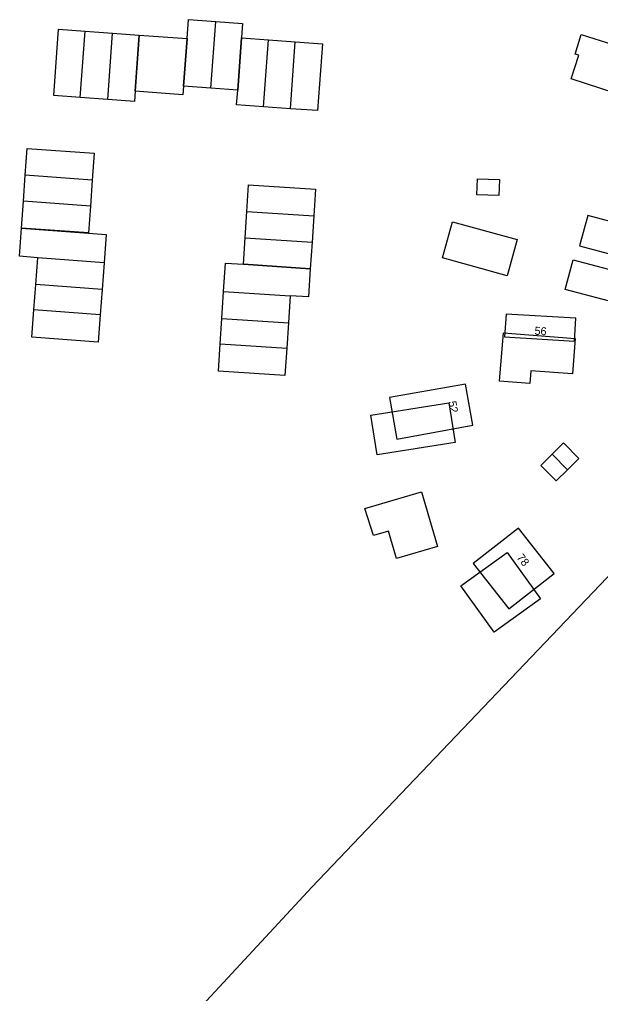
# Model space of a CAD drawing. Extents: x 159451 to 160663, y 388402 to 389723.
# Drawn here: x 160156.5 to 160229.1, y 389378.7 to 389500.3 of the extents above; entities that cross this region are included whole.
import ezdxf

# ---------------------------------------------------------------- set-up
doc = ezdxf.new("R2010")
doc.units = 0
for name, color, linetype in [('IMGEO_Groenvoorziening', 7, 'Continuous'), ('IMGEO_Pand', 7, 'Continuous'), ('IMGEO_Pand_nummerreeks', 7, 'Continuous'), ('IMGEO_Pand_vergunning_verleend', 7, 'Continuous')]:
    doc.layers.add(name, color=color, linetype=linetype)

msp = doc.modelspace()

# ---------------------------------------------------------------- linework, layer by layer
at = {"layer": 'IMGEO_Groenvoorziening'}
msp.add_lwpolyline([(160405.31, 389464.95), (160351.63, 389481.36), (160342.65, 389466.76), (160292.24, 389495.35), (160260.8, 389462.93), (160193.04, 389391.96), (160160.93, 389357.29)], dxfattribs=at)
at = {"layer": 'IMGEO_Pand'}
for points in [[(160240.12, 389472.47), (160227.53, 389475.83), (160226.52, 389472.04), (160239.12, 389468.67), (160240.12, 389472.47)], [(160226.06, 389462.98), (160217.33, 389463.5), (160217.15, 389460.66), (160225.88, 389460.14), (160226.06, 389462.98)], [(160202.76, 389453.09), (160203.67, 389447.9), (160213.16, 389449.65), (160212.26, 389454.75), (160202.76, 389453.09)], [(160213.24, 389432.36), (160217.67, 389426.68), (160223.33, 389431.12), (160218.9, 389436.78), (160213.24, 389432.36)]]:
    msp.add_lwpolyline(points, dxfattribs=at)
at = {"layer": 'IMGEO_Pand_vergunning_verleend'}
for points in [[(160177.46, 389497.91), (160177.63, 389500.3), (160181.04, 389500.05)], [(160180.44, 389491.72), (160181.04, 389500.05)], [(160181.04, 389500.05), (160184.39, 389499.81), (160184.26, 389497.99)], [(160164.11, 389490.56), (160160.8, 389490.8), (160161.39, 389499.08), (160164.71, 389498.84)], [(160164.11, 389490.56), (160164.71, 389498.84)], [(160164.71, 389498.84), (160168.16, 389498.59)], [(160167.56, 389490.31), (160168.16, 389498.59)], [(160168.16, 389498.59), (160171.49, 389498.34)], [(160170.99, 389491.33), (160170.99, 389491.33), (160171.49, 389498.34)], [(160171.49, 389498.34), (160170.99, 389491.33)], [(160171.49, 389498.34), (160177.46, 389497.91)], [(160225.46, 389492.87), (160226.41, 389495.84), (160225.95, 389495.99), (160226.73, 389498.44), (160233.07, 389496.41), (160232.26, 389493.88), (160231.88, 389494), (160230.95, 389491.1), (160225.46, 389492.87)], [(160177.46, 389497.91), (160176.95, 389490.89), (160170.99, 389491.33)], [(160180.44, 389491.72), (160177.03, 389491.97), (160177.46, 389497.91)], [(160183.79, 389491.48), (160184.26, 389497.99), (160184.26, 389497.99)], [(160184.26, 389497.99), (160183.79, 389491.48)], [(160184.26, 389497.99), (160187.63, 389497.75)], [(160187.02, 389489.4), (160187.63, 389497.75)], [(160187.63, 389497.75), (160190.98, 389497.5)], [(160190.38, 389489.16), (160190.98, 389497.5)], [(160190.98, 389497.5), (160194.38, 389497.26), (160193.78, 389488.92), (160190.38, 389489.16)], [(160170.99, 389491.33), (160170.9, 389490.07), (160167.56, 389490.31)], [(160183.79, 389491.48), (160180.44, 389491.72)], [(160187.02, 389489.4), (160183.66, 389489.65), (160183.79, 389491.48)], [(160167.56, 389490.31), (160164.11, 389490.56)], [(160190.38, 389489.16), (160187.02, 389489.4)], [(160157.25, 389480.84), (160157.5, 389484.2), (160165.86, 389483.6), (160165.62, 389480.24)], [(160157.02, 389477.6), (160157.25, 389480.84)], [(160165.62, 389480.24), (160157.25, 389480.84)], [(160165.62, 389480.24), (160165.38, 389477)], [(160213.69, 389478.42), (160213.76, 389480.41), (160216.49, 389480.32), (160216.42, 389478.32), (160213.69, 389478.42)], [(160184.94, 389476.31), (160185.16, 389479.64), (160193.52, 389479.1), (160193.3, 389475.76)], [(160156.78, 389474.25), (160157.02, 389477.6)], [(160165.38, 389477), (160157.02, 389477.6)], [(160165.38, 389477), (160165.14, 389473.65), (160156.78, 389474.25)], [(160184.73, 389473.05), (160184.94, 389476.31)], [(160184.94, 389476.31), (160193.3, 389475.76)], [(160193.3, 389475.76), (160193.08, 389472.5)], [(160209.38, 389470.53), (160210.64, 389475.05), (160218.72, 389472.81), (160217.46, 389468.29), (160209.38, 389470.53)], [(160158.81, 389470.55), (160156.52, 389470.73), (160156.78, 389474.25)], [(160156.78, 389474.25), (160167.36, 389473.46), (160167.09, 389469.93)], [(160184.51, 389469.73), (160184.73, 389473.05)], [(160184.73, 389473.05), (160193.08, 389472.5)], [(160193.08, 389472.5), (160192.86, 389469.18)], [(160158.56, 389467.22), (160158.81, 389470.55)], [(160167.09, 389469.93), (160158.81, 389470.55)], [(160224.72, 389466.58), (160225.7, 389470.29), (160238.18, 389466.99), (160237.2, 389463.29), (160224.72, 389466.58)], [(160167.09, 389469.93), (160166.84, 389466.6)], [(160182.03, 389466.35), (160182.26, 389469.88), (160184.51, 389469.73)], [(160184.51, 389469.73), (160192.86, 389469.18)], [(160192.86, 389469.18), (160184.51, 389469.73), (160184.51, 389469.73)], [(160192.86, 389469.18), (160192.63, 389465.66), (160190.36, 389465.81)], [(160158.32, 389464.04), (160158.56, 389467.22)], [(160166.84, 389466.6), (160158.56, 389467.22)], [(160166.84, 389466.6), (160166.61, 389463.42)], [(160181.81, 389462.95), (160182.03, 389466.35)], [(160182.03, 389466.35), (160190.36, 389465.81)], [(160190.36, 389465.81), (160190.13, 389462.4)], [(160166.61, 389463.42), (160166.35, 389460.02), (160158.07, 389460.64), (160158.32, 389464.04)], [(160166.61, 389463.42), (160158.32, 389464.04)], [(160181.6, 389459.79), (160181.81, 389462.95)], [(160181.81, 389462.95), (160190.13, 389462.4)], [(160190.13, 389462.4), (160189.93, 389459.25)], [(160216.53, 389455.13), (160216.99, 389461.15), (160225.98, 389460.46), (160225.64, 389456.03), (160220.43, 389456.43), (160220.31, 389454.84), (160216.53, 389455.13)], [(160189.93, 389459.25), (160189.7, 389455.84), (160181.38, 389456.39), (160181.6, 389459.79)], [(160181.6, 389459.79), (160189.93, 389459.25)], [(160200.44, 389450.89), (160210.16, 389452.44), (160210.95, 389447.48), (160201.24, 389445.93), (160200.44, 389450.89)], [(160223.08, 389446.02), (160224.49, 389447.42), (160226.41, 389445.48), (160225, 389444.08)], [(160225, 389444.08), (160223.59, 389442.68), (160221.67, 389444.62), (160223.08, 389446.02)], [(160223.08, 389446.02), (160225, 389444.08)], [(160199.68, 389439.25), (160206.78, 389441.32), (160208.77, 389434.49), (160203.62, 389432.99), (160202.62, 389436.41), (160200.76, 389435.87), (160199.68, 389439.25)], [(160211.68, 389429.57), (160217.45, 389433.75), (160221.62, 389427.97), (160215.85, 389423.8), (160211.68, 389429.57)]]:
    msp.add_lwpolyline(points, dxfattribs=at)

# ---------------------------------------------------------------- texts
at = {"layer": 'IMGEO_Pand_nummerreeks'}
for s, rotation, p in [('56', 356.631, (160220.87, 389460.94)), ('52', 279.9406, (160210.11, 389452.57)), ('78', 308.0556, (160218.61, 389433.09))]:
    msp.add_text(s, height=1, rotation=rotation, dxfattribs=at).set_placement(p)

doc.saveas('drawing.dxf')
